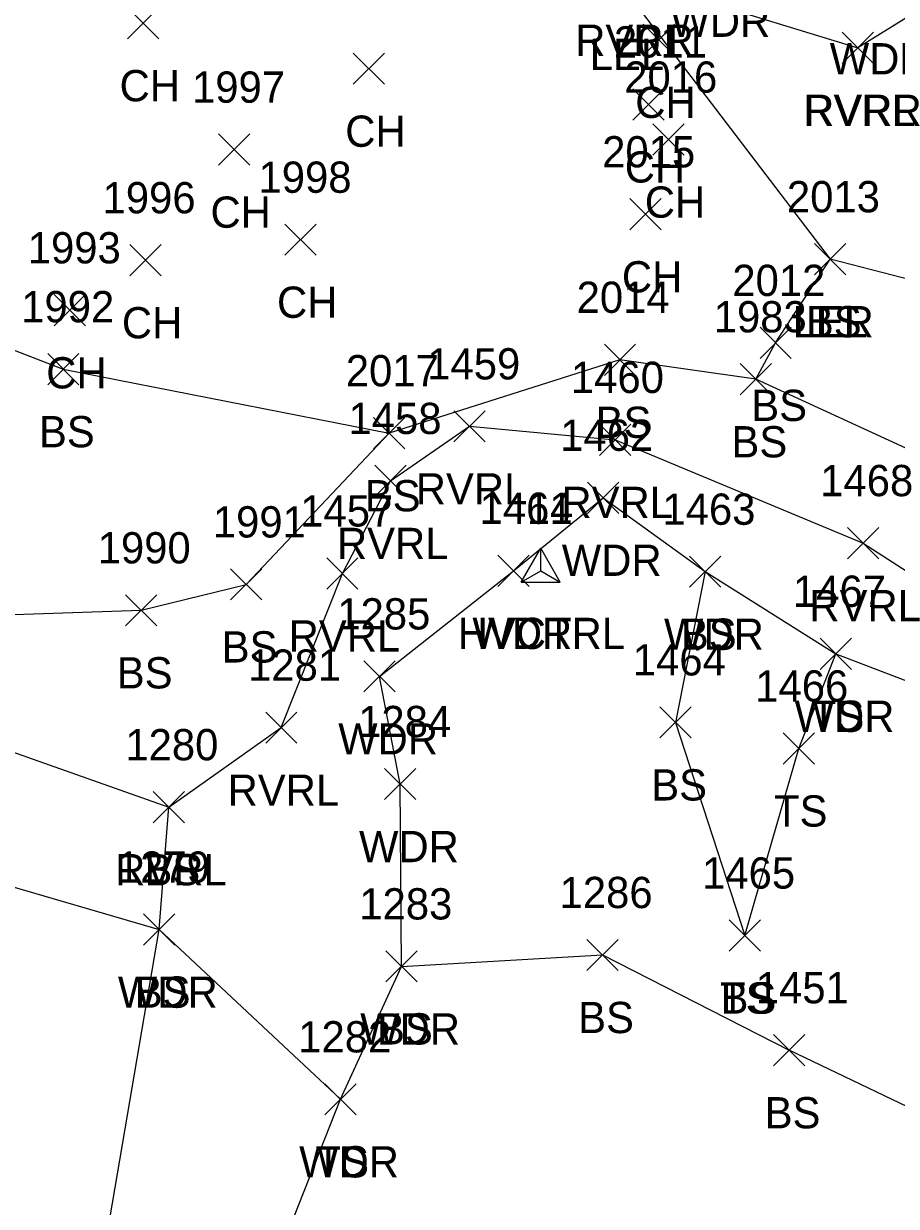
# Model space of a CAD drawing. Extents: x 1600281 to 1602254, y 862855 to 863227.
# Drawn here: x 1601927.2 to 1601983.1, y 863026.2 to 863101.9 of the extents above; entities that cross this region are included whole.
import ezdxf

# ---------------------------------------------------------------- set-up
doc = ezdxf.new("R2010")
doc.units = 0
for name, color, linetype in [('C_A', 7, 'Continuous'), ('C_I', 7, 'Continuous'), ('CPSM', 7, 'Continuous'), ('L_A', 7, 'Continuous'), ('L_I', 7, 'Continuous'), ('L_TIC', 7, 'Continuous'), ('LARO', 7, 'Continuous'), ('LAWA', 7, 'Continuous'), ('LAWE', 7, 'Continuous'), ('LELB', 7, 'Continuous')]:
    doc.layers.add(name, color=color, linetype=linetype)

msp = doc.modelspace()

# ---------------------------------------------------------------- linework, layer by layer
at = {"layer": 'CPSM'}
for p, q in [((1601959.061, 863066.114), (1601960.311, 863068.279)), ((1601961.561, 863066.114), (1601960.311, 863068.279)), ((1601960.311, 863066.835), (1601960.311, 863068.279)), ((1601959.061, 863066.114), (1601960.311, 863066.835)), ((1601960.311, 863066.835), (1601960.311, 863066.835)), ((1601960.311, 863066.835), (1601961.561, 863066.114)), ((1601959.061, 863066.114), (1601961.561, 863066.114))]:
    msp.add_line(p, q, dxfattribs=at)
at = {"layer": 'L_TIC'}
for points in [[(1601933.888, 863100.884), (1601935.888, 863102.884)], [(1601935.888, 863100.884), (1601933.888, 863102.884)], [(1601966.867, 863099.816), (1601968.867, 863101.816)], [(1601968.867, 863099.816), (1601966.867, 863101.816)], [(1601979.589, 863099.305), (1601981.589, 863101.305)], [(1601981.589, 863099.305), (1601979.589, 863101.305)], [(1601979.589, 863099.305), (1601981.589, 863101.305)], [(1601981.589, 863099.305), (1601979.589, 863101.305)], [(1601948.319, 863097.973), (1601950.319, 863099.973)], [(1601950.319, 863097.973), (1601948.319, 863099.973)], [(1601966.194, 863095.684), (1601968.194, 863097.684)], [(1601968.194, 863095.684), (1601966.194, 863097.684)], [(1601967.476, 863093.435), (1601969.476, 863095.435)], [(1601969.476, 863093.435), (1601967.476, 863095.435)], [(1601939.701, 863092.793), (1601941.701, 863094.793)], [(1601941.701, 863092.793), (1601939.701, 863094.793)], [(1601966.01, 863088.654), (1601968.01, 863090.654)], [(1601968.01, 863088.654), (1601966.01, 863090.654)], [(1601943.953, 863087.029), (1601945.953, 863089.029)], [(1601945.953, 863087.029), (1601943.953, 863089.029)], [(1601977.825, 863085.781), (1601979.825, 863087.781)], [(1601979.825, 863085.781), (1601977.825, 863087.781)], [(1601977.825, 863085.781), (1601979.825, 863087.781)], [(1601979.825, 863085.781), (1601977.825, 863087.781)], [(1601977.825, 863085.781), (1601979.825, 863087.781)], [(1601979.825, 863085.781), (1601977.825, 863087.781)], [(1601934.034, 863085.716), (1601936.034, 863087.716)], [(1601936.034, 863085.716), (1601934.034, 863087.716)], [(1601929.195, 863082.511), (1601931.195, 863084.511)], [(1601931.195, 863082.511), (1601929.195, 863084.511)], [(1601974.334, 863080.426), (1601976.334, 863082.426)], [(1601976.334, 863080.426), (1601974.334, 863082.426)], [(1601964.377, 863079.345), (1601966.377, 863081.345)], [(1601966.377, 863079.345), (1601964.377, 863081.345)], [(1601928.776, 863078.744), (1601930.776, 863080.744)], [(1601930.776, 863078.744), (1601928.776, 863080.744)], [(1601973.066, 863078.098), (1601975.066, 863080.098)], [(1601975.066, 863078.098), (1601973.066, 863080.098)], [(1601973.066, 863078.098), (1601975.066, 863080.098)], [(1601975.066, 863078.098), (1601973.066, 863080.098)], [(1601949.615, 863074.646), (1601951.615, 863076.646)], [(1601951.615, 863074.646), (1601949.615, 863076.646)], [(1601949.615, 863074.646), (1601951.615, 863076.646)], [(1601951.615, 863074.646), (1601949.615, 863076.646)], [(1601949.615, 863074.646), (1601951.615, 863076.646)], [(1601951.615, 863074.646), (1601949.615, 863076.646)], [(1601954.751, 863075.087), (1601956.751, 863077.087)], [(1601956.751, 863075.087), (1601954.751, 863077.087)], [(1601964.067, 863074.219), (1601966.067, 863076.219)], [(1601966.067, 863074.219), (1601964.067, 863076.219)], [(1601949.709, 863071.592), (1601951.709, 863073.592)], [(1601951.709, 863071.592), (1601949.709, 863073.592)], [(1601963.294, 863070.516), (1601965.294, 863072.516)], [(1601965.294, 863070.516), (1601963.294, 863072.516)], [(1601979.923, 863067.616), (1601981.923, 863069.616)], [(1601981.923, 863067.616), (1601979.923, 863069.616)], [(1601946.621, 863065.675), (1601948.621, 863067.675)], [(1601948.621, 863065.675), (1601946.621, 863067.675)], [(1601957.573, 863065.845), (1601959.573, 863067.845)], [(1601959.573, 863065.845), (1601957.573, 863067.845)], [(1601969.831, 863065.786), (1601971.831, 863067.786)], [(1601971.831, 863065.786), (1601969.831, 863067.786)], [(1601969.831, 863065.786), (1601971.831, 863067.786)], [(1601971.831, 863065.786), (1601969.831, 863067.786)], [(1601940.464, 863064.973), (1601942.464, 863066.973)], [(1601942.464, 863064.973), (1601940.464, 863066.973)], [(1601933.755, 863063.314), (1601935.755, 863065.314)], [(1601935.755, 863063.314), (1601933.755, 863065.314)], [(1601978.179, 863060.535), (1601980.179, 863062.535)], [(1601980.179, 863060.535), (1601978.179, 863062.535)], [(1601978.179, 863060.535), (1601980.179, 863062.535)], [(1601980.179, 863060.535), (1601978.179, 863062.535)], [(1601948.991, 863059.087), (1601950.991, 863061.087)], [(1601950.991, 863059.087), (1601948.991, 863061.087)], [(1601942.718, 863055.806), (1601944.718, 863057.806)], [(1601944.718, 863055.806), (1601942.718, 863057.806)], [(1601967.936, 863056.143), (1601969.936, 863058.143)], [(1601969.936, 863056.143), (1601967.936, 863058.143)], [(1601975.822, 863054.473), (1601977.822, 863056.473)], [(1601977.822, 863054.473), (1601975.822, 863056.473)], [(1601950.325, 863052.197), (1601952.325, 863054.197)], [(1601952.325, 863052.197), (1601950.325, 863054.197)], [(1601935.523, 863050.716), (1601937.523, 863052.716)], [(1601937.523, 863050.716), (1601935.523, 863052.716)], [(1601935.523, 863050.716), (1601937.523, 863052.716)], [(1601937.523, 863050.716), (1601935.523, 863052.716)], [(1601934.902, 863042.881), (1601936.902, 863044.881)], [(1601936.902, 863042.881), (1601934.902, 863044.881)], [(1601934.902, 863042.881), (1601936.902, 863044.881)], [(1601936.902, 863042.881), (1601934.902, 863044.881)], [(1601972.368, 863042.506), (1601974.368, 863044.506)], [(1601974.368, 863042.506), (1601972.368, 863044.506)], [(1601972.368, 863042.506), (1601974.368, 863044.506)], [(1601974.368, 863042.506), (1601972.368, 863044.506)], [(1601963.262, 863041.258), (1601965.262, 863043.258)], [(1601965.262, 863041.258), (1601963.262, 863043.258)], [(1601950.399, 863040.53), (1601952.399, 863042.53)], [(1601952.399, 863040.53), (1601950.399, 863042.53)], [(1601950.399, 863040.53), (1601952.399, 863042.53)], [(1601952.399, 863040.53), (1601950.399, 863042.53)], [(1601975.19, 863035.164), (1601977.19, 863037.164)], [(1601977.19, 863035.164), (1601975.19, 863037.164)], [(1601975.19, 863035.164), (1601977.19, 863037.164)], [(1601977.19, 863035.164), (1601975.19, 863037.164)], [(1601946.495, 863032.023), (1601948.495, 863034.023)], [(1601948.495, 863032.023), (1601946.495, 863034.023)], [(1601946.495, 863032.023), (1601948.495, 863034.023)], [(1601948.495, 863032.023), (1601946.495, 863034.023)]]:
    msp.add_lwpolyline(points, dxfattribs=at)
at = {"layer": 'LARO'}
for points in [[(1601924.225, 863126.195), (1601937.743, 863114.803), (1601944.42, 863113.097), (1601965.803, 863103.882), (1601978.825, 863086.781)], [(1602088.591, 863055.936), (1602084.205, 863057.115), (1602072.763, 863055.569), (1602061.695, 863058.699), (1602046.297, 863060.847), (1602041.29, 863063.794), (1602038.414, 863067.763), (1602029.525, 863077.549), (1602024.193, 863078.94), (1602013.468, 863079.959), (1602006.072, 863081.659), (1601997.978, 863081.824), (1601978.825, 863086.781)]]:
    msp.add_lwpolyline(points, dxfattribs=at)
at = {"layer": 'LAWA'}
msp.add_lwpolyline([(1601898.678, 863064.416), (1601911.709, 863050.949), (1601935.902, 863043.881), (1601947.495, 863033.023), (1601951.399, 863041.53), (1601951.325, 863053.197), (1601949.991, 863060.087), (1601958.573, 863066.845), (1601964.294, 863071.516), (1601970.831, 863066.786), (1601979.179, 863061.535), (1601987.871, 863058.21), (1601991.577, 863057.216), (1602006.602, 863051.128), (1602014.671, 863047.985), (1602025.678, 863046.601), (1602024.954, 863036.82), (1602020.118, 863030.26)], dxfattribs=at)
at = {"layer": 'LAWE'}
for points in [[(1601925.466, 863126.753), (1601938.503, 863115.681), (1601944.93, 863112.985), (1601966.005, 863104.792), (1601980.589, 863100.305)], [(1602053.378, 863085.572), (1602049.014, 863088.599), (1602037.877, 863092.461), (1602027.14, 863095.153), (1602014.534, 863094.667), (1602004.691, 863100.661), (1601989.462, 863105.807), (1601980.589, 863100.305)], [(1601898.678, 863064.416), (1601916.681, 863058.738), (1601936.523, 863051.716), (1601943.718, 863056.806), (1601947.621, 863066.675), (1601950.709, 863072.592), (1601955.751, 863076.087), (1601965.067, 863075.219), (1601980.923, 863068.616), (1601992.557, 863061.13), (1602010.649, 863053.195), (1602028.102, 863054.194), (1602030.833, 863052.803)]]:
    msp.add_lwpolyline(points, dxfattribs=at)
at = {"layer": 'LELB'}
for points in [[(1601974.066, 863079.098), (1601975.334, 863081.426), (1601978.825, 863086.781)], [(1601906.996, 863085.564), (1601921.219, 863083.052), (1601929.776, 863079.744), (1601950.615, 863075.646)], [(1602030.177, 863055.597), (1602022.043, 863055.22), (1602010.309, 863056.702), (1602006.388, 863056.918), (1602003.277, 863059.068), (1602000.504, 863068.388), (1601985.789, 863073.704), (1601974.066, 863079.098), (1601965.377, 863080.345), (1601950.615, 863075.646)], [(1601899.695, 863069.557), (1601915.964, 863063.675), (1601934.755, 863064.314), (1601941.464, 863065.973), (1601950.615, 863075.646)], [(1601970.831, 863066.786), (1601968.936, 863057.143), (1601973.368, 863043.506)], [(1601889.548, 862979.701), (1601879.53, 862980.196), (1601869.363, 862989.31), (1601873.745, 863000.271), (1601884.058, 863016.502), (1601890.014, 863028.231), (1601890.388, 863044.156), (1601893.555, 863052.296), (1601898.678, 863064.416), (1601898.005, 863054.108), (1601899.316, 863041.878), (1601901.962, 863029.12), (1601931.055, 863015.369), (1601935.902, 863043.881), (1601936.523, 863051.716)], [(1601973.368, 863043.506), (1601976.822, 863055.473), (1601979.179, 863061.535)], [(1601881.596, 863023.768), (1601884.862, 863033.619), (1601890.388, 863044.156), (1601893.063, 863038.692), (1601893.536, 863030.212), (1601909.571, 863016.62), (1601907.502, 863002.961), (1601921.846, 863001.516), (1601937.517, 863007.754), (1601947.495, 863033.023)], [(1601951.399, 863041.53), (1601964.262, 863042.258), (1601976.19, 863036.164)], [(1601958.999, 862928.536), (1601972.89, 862929.468), (1601981.162, 862933.435), (1601993.258, 862937.414), (1602005.114, 862948.359), (1602014.99, 862961.982), (1602017.327, 862980.602), (1602012.478, 863001.488), (1602005.728, 863016.362), (1601997.522, 863019.91), (1601988.341, 863030.346), (1601976.19, 863036.164)]]:
    msp.add_lwpolyline(points, dxfattribs=at)

# ---------------------------------------------------------------- texts
at = {"layer": 'C_A'}
msp.add_text('HVCTRL', height=2, dxfattribs=at).set_placement((1601955.004, 863061.835))
at = {"layer": 'C_I'}
msp.add_text('14', height=2, dxfattribs=at).set_placement((1601959.414, 863069.835))
at = {"layer": 'L_A'}
for s, p in [('WDR', (1601968.6, 863101.008)), ('RVRR', (1601962.516, 863099.792)), ('LEL', (1601963.441, 863098.882)), ('WDR', (1601978.791, 863098.605)), ('CH', (1601933.376, 863096.884)), ('CH', (1601966.355, 863095.816)), ('RVRR', (1601977.101, 863095.305)), ('RVRL', (1601977.156, 863095.305)), ('CH', (1601947.807, 863093.973)), ('CH', (1601965.682, 863091.684)), ('CH', (1601939.189, 863088.793)), ('CH', (1601966.964, 863089.435)), ('CH', (1601965.499, 863084.654)), ('CH', (1601943.442, 863083.029)), ('CH', (1601933.522, 863081.716)), ('LER', (1601976.408, 863081.781)), ('LEL', (1601976.463, 863081.781)), ('BS', (1601977.266, 863081.781)), ('CH', (1601928.683, 863078.511)), ('BS', (1601973.775, 863076.426)), ('BS', (1601963.818, 863075.345)), ('BS', (1601928.217, 863074.744)), ('BS', (1601972.507, 863074.098)), ('BS', (1601972.507, 863074.098)), ('BS', (1601949.056, 863070.646)), ('BS', (1601949.056, 863070.646)), ('BS', (1601949.056, 863070.646)), ('RVRL', (1601952.318, 863071.087)), ('RVRL', (1601961.634, 863070.219)), ('RVRL', (1601947.276, 863067.592)), ('WDR', (1601961.656, 863066.516)), ('RVRL', (1601977.49, 863063.616)), ('RVRL', (1601944.188, 863061.675)), ('WDR', (1601955.935, 863061.845)), ('WDR', (1601968.193, 863061.786)), ('BS', (1601969.272, 863061.786)), ('BS', (1601939.905, 863060.973)), ('BS', (1601933.196, 863059.314)), ('WDR', (1601976.541, 863056.535)), ('TS', (1601977.588, 863056.535)), ('WDR', (1601947.354, 863055.087)), ('RVRL', (1601940.285, 863051.806)), ('BS', (1601967.377, 863052.143)), ('TS', (1601975.231, 863050.473)), ('WDR', (1601948.687, 863048.197)), ('RVRL', (1601933.09, 863046.716)), ('BS', (1601934.964, 863046.716)), ('WDR', (1601933.264, 863038.881)), ('BS', (1601934.343, 863038.881)), ('TS', (1601971.778, 863038.506)), ('BS', (1601971.809, 863038.506)), ('BS', (1601962.703, 863037.258)), ('WDR', (1601948.761, 863036.53)), ('BS', (1601949.84, 863036.53)), ('BS', (1601974.631, 863031.164)), ('BS', (1601974.631, 863031.164)), ('WDR', (1601944.857, 863028.023)), ('TS', (1601945.904, 863028.023))]:
    msp.add_text(s, height=2, dxfattribs=at).set_placement(p)
at = {"layer": 'L_I'}
for s, p in [('2011', (1601964.989, 863099.684)), ('2016', (1601965.649, 863097.435)), ('1997', (1601938.008, 863096.793)), ('2015', (1601964.239, 863092.654)), ('1998', (1601942.26, 863091.029)), ('1996', (1601932.286, 863089.716)), ('2013', (1601976.053, 863089.781)), ('2013', (1601976.053, 863089.781)), ('2013', (1601976.053, 863089.781)), ('1993', (1601927.502, 863086.511)), ('2012', (1601972.563, 863084.426)), ('1992', (1601927.083, 863082.744)), ('2014', (1601962.606, 863083.345)), ('1983', (1601971.373, 863082.098)), ('1983', (1601971.373, 863082.098)), ('1459', (1601953.05, 863079.087)), ('2017', (1601947.843, 863078.646)), ('2017', (1601947.843, 863078.646)), ('2017', (1601947.843, 863078.646)), ('1460', (1601962.24, 863078.219)), ('1458', (1601948.016, 863075.592)), ('1462', (1601961.553, 863074.516)), ('1468', (1601978.183, 863071.616)), ('1461', (1601956.399, 863069.845)), ('1457', (1601944.928, 863069.675)), ('1463', (1601968.091, 863069.786)), ('1463', (1601968.091, 863069.786)), ('1991', (1601939.338, 863068.973)), ('1990', (1601931.975, 863067.314)), ('1467', (1601976.438, 863064.535)), ('1467', (1601976.438, 863064.535)), ('1285', (1601947.299, 863063.087)), ('1464', (1601966.196, 863060.143)), ('1281', (1601941.592, 863059.806)), ('1466', (1601974.027, 863058.473)), ('1284', (1601948.632, 863056.197)), ('1280', (1601933.743, 863054.716)), ('1280', (1601933.743, 863054.716)), ('1279', (1601933.201, 863046.881)), ('1279', (1601933.201, 863046.881)), ('1465', (1601970.628, 863046.506)), ('1465', (1601970.628, 863046.506)), ('1286', (1601961.514, 863045.258)), ('1283', (1601948.706, 863044.53)), ('1283', (1601948.706, 863044.53)), ('1451', (1601974.064, 863039.164)), ('1451', (1601974.064, 863039.164)), ('1282', (1601944.802, 863036.023)), ('1282', (1601944.802, 863036.023))]:
    msp.add_text(s, height=2, dxfattribs=at).set_placement(p)

doc.saveas('drawing.dxf')
